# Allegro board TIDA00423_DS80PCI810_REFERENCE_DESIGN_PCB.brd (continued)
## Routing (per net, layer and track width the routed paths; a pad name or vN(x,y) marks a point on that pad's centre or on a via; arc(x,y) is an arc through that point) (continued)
N144795421: length 28.1
  BOTTOM w0.203: C155.2 116.9,46.44 116.9,48.04 118.07,49.21 127.42,49.21 128.56,50.35 128.56,53.83 126.53,55.86 124.14,55.86 122.9,57.11 122.9,60 J2.A76
N144795720: length 39.6
  TOP w0.203: J2.B51 97.37,59.97 97.37,55.89 99.87,53.39 103.7,53.39 104.66,52.42 104.66,48.52 102.78,46.64 102.78,36.2 106.31,32.67 108.76,32.67 109.44,32 109.44,31.19 C112.1
N144796260: length 39.9
  TOP w0.203: C105.1 70.78,31.19 70.78,32.95 73.56,35.73 77.89,35.73 78.65,36.49 78.65,44.9 77.27,46.28 77.27,51.81 79.79,54.33 82.2,54.33 83.95,56.08 83.95,59.95 J2.B37
N144796741: length 28.3
  BOTTOM w0.203: J2.A69 115.37,59.96 115.37,54.74 115.96,54.14 122.27,54.14 123.09,53.32 123.09,51.94 122.24,51.09 115.6,51.09 114.73,50.22 114.73,46.44 C152.2
N144796981: length 28.2
  BOTTOM w0.203: C136.2 69.91,46.45 69.91,49.95 71.5,51.54 83.34,51.54 84.8,53 84.8,55.26 82.38,57.68 82.38,59.98 J2.A36
N144870501: length 4.1
  TOP w0.292: SW2.3 v1(20.38,53.36)
  BOTTOM w0.292: R19.2 20.26,53.24 v1(20.38,53.36)
N144870781: length 3.9
  TOP w0.292: SW2.1 v1(25.46,53.26)
  BOTTOM w0.292: R17.2 v1(25.46,53.26)
N144871281: length 4.1
  TOP w0.292: SW2.2 v1(22.92,53.36)
  BOTTOM w0.292: R18.2 v1(22.92,53.36)
N144872111: length 2.8
  TOP w0.292: SW3.6 v1(30.29,32.43)
  BOTTOM w0.292: R25.2 v1(30.29,32.43)
N144872810: length 2.8
  TOP w0.292: SW3.1 v1(17.59,32.43)
  BOTTOM w0.292: R20.2 v1(17.59,32.43)
N144872811: length 2.8
  TOP w0.292: 20.13,30.77 v1(20.13,32.43)
  BOTTOM w0.292: R21.2 v1(20.13,32.43)
N144872812: length 2.8
  TOP w0.292: SW3.3 v1(22.67,32.43)
  BOTTOM w0.292: R22.2 v1(22.67,32.43)
N144872813: length 2.8
  TOP w0.292: 25.21,30.77 v1(25.21,32.43)
  BOTTOM w0.292: v1(25.21,32.43) 25.08,32.56 R23.2
N144872814: length 2.8
  TOP w0.292: SW3.5 v1(27.75,32.43)
  BOTTOM w0.292: R24.2 v1(27.75,32.43)
N144873671: length 3.1
  TOP w0.292: SW5.4 v1(25.46,19.86)
  BOTTOM w0.292: R29.2 v1(25.46,19.86)
N144874091: length 3.1
  TOP w0.292: SW5.6 v1(30.54,19.86)
  BOTTOM w0.292: R31.2 v1(30.54,19.86)
N144874331: length 3.1
  TOP w0.292: 28,17.95 v1(28,19.86)
  BOTTOM w0.292: R30.2 v1(28,19.86)
N144874811: length 3.1
  TOP w0.292: 22.92,17.95 v1(22.92,19.86)
  BOTTOM w0.292: R28.2 v1(22.92,19.86)
N144875811: length 3.1
  TOP w0.292: 17.84,17.95 v1(17.84,19.86)
  BOTTOM w0.292: R26.2 v1(17.84,19.86)
N144876491: length 3.1
  TOP w0.292: SW5.2 v1(20.38,19.86)
  BOTTOM w0.292: R27.2 v1(20.38,19.86)
N144883340: length 3
  TOP w0.292: SW10.1 v1(159.65,37.06)
  BOTTOM w0.292: R38.2 159.4,36.8 v1(159.65,37.06)
N144883341: length 3.1
  TOP w0.292: SW10.2 v1(159.65,39.6)
  BOTTOM w0.292: R39.2 159.53,39.47 v1(159.65,39.6)
N144883342: length 3.2
  TOP w0.292: SW10.3 v1(159.65,42.14)
  BOTTOM w0.292: v1(159.65,42.14) 159.53,42.01 R40.2
N144883343: length 3.2
  TOP w0.292: SW10.4 v1(159.65,44.68)
  BOTTOM w0.292: R41.2 159.53,44.55 v1(159.65,44.68)
N144883344: length 3.2
  TOP w0.292: SW10.5 v1(159.65,47.22)
  BOTTOM w0.292: R42.2 159.53,47.09 v1(159.65,47.22)
N144883345: length 3.2
  TOP w0.292: SW10.6 v1(159.65,49.76)
  BOTTOM w0.292: v1(159.65,49.76) 159.53,49.63 R43.2
N144883781: length 2.8
  TOP w0.292: SW11.1 v1(159.75,18.77)
  BOTTOM w0.292: R44.2 v1(159.75,18.77)
N144885701: length 2.9
  TOP w0.292: SW6.4 v1(147.31,56.99)
  BOTTOM w0.292: R35.2 147.05,56.74 v1(147.31,56.99)
N144886021: length 2.8
  TOP w0.292: SW11.2 v1(159.75,21.31)
  BOTTOM w0.292: R45.2 v1(159.75,21.31)
N144886681: length 2.9
  TOP w0.292: SW6.6 v1(147.18,62.07)
  BOTTOM w0.292: R37.2 147.05,61.95 v1(147.18,62.07)
N144886921: length 2.8
  TOP w0.292: SW6.5 v1(147.31,59.53)
  BOTTOM w0.292: v1(147.31,59.53) 147.18,59.41 R36.2
N144888121: length 2.8
  TOP w0.292: SW6.3 v1(147.31,54.45)
  BOTTOM w0.292: v1(147.31,54.45) 147.18,54.33 R34.2
N144888661: length 3
  TOP w0.292: SW11.6 v1(159.75,31.47)
  BOTTOM w0.292: R49.2 v1(159.75,31.47)
N144889101: length 2.9
  TOP w0.292: SW11.3 v1(159.75,23.85)
  BOTTOM w0.292: R46.2 v1(159.75,23.85)
N144890181: length 2.9
  TOP w0.292: SW11.4 v1(159.75,26.39)
  BOTTOM w0.292: R47.2 v1(159.75,26.39)
N144890984: length 2.9
  TOP w0.292: SW11.5 v1(159.78,28.93)
  BOTTOM w0.292: R48.2 v1(159.78,28.93)
N144891221: length 2.9
  TOP w0.292: SW6.1 v1(147.31,49.37)
  BOTTOM w0.292: v1(147.31,49.37) 147.05,49.12 R32.2
N144891941: length 2.8
  TOP w0.292: SW6.2 v1(147.31,51.91)
  BOTTOM w0.292: v1(147.31,51.91) 147.18,51.79 R33.2
N144905650: length 1.9
  TOP w0.292: D1.2 R7.1
N144909880: length 1.9
  TOP w0.292: D3.2 R9.1
N144912360: length 1.9
  TOP w0.292: D2.2 R8.1
N144914850: length 1.9
  TOP w0.292: D4.2 R10.1
N708449615: length 39.6
  BOTTOM w0.203: J1.A16 62.92,3.8 62.92,12.35 54.67,20.61 54.67,27.09 59.52,31.94 63.6,31.94 64.17,32.52 64.17,33.06 64.07,33.16 C63.2
N708449616: length 39.6
  BOTTOM w0.203: J1.A17 63.38,3.81 63.38,12.54 55.12,20.8 55.12,26.9 59.7,31.48 63.79,31.48 64.63,32.33 64.63,33.12 C64.2
N708449620: length 39.9
  BOTTOM w0.203: C65.2 65.5,33.12 65.5,32.34 63.88,30.73 60.55,30.73 56.88,27.06 56.88,20.77 67.92,9.73 67.92,3.81 J1.A21
N708449621: length 39.9
  BOTTOM w0.203: J1.A22 68.38,3.81 68.38,9.92 57.34,20.96 57.34,26.87 60.74,30.27 64.07,30.27 65.95,32.15 65.95,33.12 C66.2
N708449624: length 39.8
  BOTTOM w0.203: J1.A25 71.92,3.81 71.92,8.04 59.34,20.62 59.34,27.33 61.63,29.62 64.43,29.62 66.82,32.01 66.82,33.12 C67.2
N708449625: length 39.8
  BOTTOM w0.203: C68.2 67.28,33.12 67.28,31.82 64.62,29.16 61.82,29.16 59.8,27.14 59.8,20.81 72.38,8.23 72.38,3.81 J1.A26
N708449628: length 39.9
  BOTTOM w0.203: J1.A29 75.92,3.81 75.92,6.85 61.25,21.52 61.25,26.79 62.87,28.41 64.83,28.41 68.14,31.73 68.14,33.11 C69.2
N708449629: length 39.9
  BOTTOM w0.203: C70.2 68.6,33.13 68.6,31.54 65.02,27.96 63.06,27.96 61.71,26.61 61.71,21.71 76.38,7.04 76.38,3.81 J1.A30
N708449634: length 39.9
  BOTTOM w0.203: C71.2 69.46,33.11 69.46,30.2 71.62,28.04 75.25,28.04 77.46,25.83 77.46,21.54 75.29,19.38 75.29,13.01 78.55,9.76 80.27,9.76 81.92,8.12 81.92,3.81 J1.A35
N708449635: length 39.9
  BOTTOM w0.203: J1.A36 82.38,3.81 82.38,8.31 80.46,10.22 78.73,10.22 75.75,13.2 75.75,19.19 77.91,21.35 77.91,26.02 75.44,28.5 71.81,28.5 69.92,30.39 69.92,33.12 C72.2
N708449638: length 39.9
  BOTTOM w0.203: J1.A39 85.92,3.81 85.92,9.43 83.6,11.75 80.55,11.75 79.23,13.07 79.23,14.97 79.23,25.52 75.58,29.17 72.09,29.17 70.81,30.45 70.81,33.09 C73.2
N708449639: length 39.9
  BOTTOM w0.203: C74.2 71.27,33.15 71.27,30.64 72.28,29.63 75.77,29.63 79.69,25.71 79.69,15.16 79.69,13.26 80.74,12.21 83.79,12.21 86.38,9.62 86.38,3.81 J1.A40
N708449642: length 40.1
  BOTTOM w0.203: J1.A43 89.92,3.81 89.92,9.95 85.85,14.03 83.71,14.03 80.6,17.13 80.6,25.72 76.05,30.28 73.25,30.28 72.1,31.43 72.1,33.11 C75.2
N708449643: length 40.1
  BOTTOM w0.203: C76.2 72.56,33.13 72.56,31.62 73.44,30.74 76.23,30.74 81.06,25.91 81.06,17.32 83.9,14.48 86.04,14.48 90.38,10.14 90.38,3.81 J1.A44
N708449646: length 39.9
  BOTTOM w0.203: J1.A47 93.92,3.81 93.92,8 81.83,20.1 81.83,26.53 76.96,31.4 74.22,31.4 73.39,32.24 73.39,33.15 C77.2
N708449647: length 40
  BOTTOM w0.203: C78.2 73.84,33.09 73.84,32.42 74.41,31.85 77.15,31.85 82.28,26.72 82.28,20.29 94.38,8.19 94.38,3.81 J1.A48
N708449651: length 39.5
  BOTTOM w0.203: C79.2 108.99,33.11 108.99,32.19 108.1,31.3 105.58,31.3 102.19,27.91 102.19,16.4 100.79,15 98.5,15 96.24,12.74 96.24,8.81 96.92,8.13 97.77,8.13 98.92,6.98 98.92,3.81 J1.A52
N708449652: length 39.5
  BOTTOM w0.203: C80.2 109.44,33.13 109.44,32 108.29,30.84 105.77,30.84 102.65,27.72 102.65,16.21 100.98,14.54 98.69,14.54 96.7,12.55 96.7,9 97.11,8.59 97.96,8.59 99.38,7.17 99.38,3.81 J1.A53
N708449655: length 39.7
  BOTTOM w0.203: J1.A56 102.92,3.81 102.92,7.41 102.06,8.28 100.15,8.28 99.2,9.23 99.2,12.15 100.25,13.2 102.76,13.2 103.46,13.89 103.46,26.52 107.12,30.18 109.03,30.18 110.31,31.46 110.31,33.11 C81.2
N708449656: length 39.7
  BOTTOM w0.203: C82.2 110.77,33.13 110.77,31.27 109.22,29.72 107.31,29.72 103.92,26.33 103.92,13.71 102.95,12.74 100.44,12.74 99.66,11.96 99.66,9.42 100.34,8.73 102.25,8.73 103.38,7.6 103.38,3.81 J1.A57
N708449659: length 40.1
  BOTTOM w0.203: C83.2 111.59,33.15 111.59,30.7 109.95,29.06 107.79,29.06 104.73,26 104.73,16.73 107.85,13.62 107.85,12.82 107.2,12.17 104.91,12.17 104.12,11.38 104.12,9.94 104.95,9.11 106.31,9.11 106.92,8.5 106.92,3.81 J1.A60
N708449660: length 40.1
  BOTTOM w0.203: C84.2 112.05,33.09 112.05,30.51 110.14,28.6 107.98,28.6 105.19,25.81 105.19,16.92 108.31,13.81 108.31,12.63 107.39,11.71 105.1,11.71 104.57,11.19 104.57,10.13 105.14,9.57 106.49,9.57 107.38,8.68 107.38,3.81 J1.A61
N708449663: length 40.2
  BOTTOM w0.203: C85.2 112.97,33.09 112.97,30.86 116.41,27.42 120.18,27.42 121.77,25.83 121.77,20.19 110.92,9.34 110.92,3.81 J1.A64
N708449664: length 40.2
  BOTTOM w0.203: J1.A65 111.38,3.81 111.38,9.15 122.23,20 122.23,26.02 120.37,27.88 116.6,27.88 113.43,31.05 113.43,33.15 C86.2
N708449667: length 40.1
  BOTTOM w0.203: J1.A68 114.89,3.78 114.89,7.02 113.94,7.97 113.94,10.28 122.97,19.31 122.97,26.92 121.49,28.4 117.2,28.4 114.27,31.33 114.27,33.12 C87.2
N708449668: length 40.1
  BOTTOM w0.203: J1.A69 115.35,3.84 115.35,7.21 114.4,8.16 114.4,10.09 123.43,19.12 123.43,27.11 121.68,28.85 117.39,28.85 114.72,31.52 114.72,33.12 C88.2
N708449671: length 39.9
  BOTTOM w0.203: C89.2 115.58,33.12 115.58,31.63 117.79,29.43 122.2,29.43 124.21,27.42 124.21,18.59 116.89,11.27 116.89,9.47 118.92,7.45 118.92,3.81 J1.A72
N708449672: length 39.9
  BOTTOM w0.203: J1.A73 119.38,3.81 119.38,7.64 117.35,9.66 117.35,11.08 124.67,18.4 124.67,27.61 122.39,29.88 117.97,29.88 116.04,31.82 116.04,33.12 C90.2
N708449675: length 39.8
  BOTTOM w0.203: C91.2 116.91,33.11 116.91,32.07 118.51,30.46 123.41,30.46 125.38,28.49 125.38,18.04 119.87,12.53 119.87,10.52 122.92,7.47 122.92,3.81 J1.A76
N708449676: length 39.8
  BOTTOM w0.203: C92.2 117.37,33.13 117.37,32.26 118.7,30.92 123.6,30.92 125.84,28.68 125.84,17.85 120.33,12.34 120.33,10.71 123.38,7.66 123.38,3.81 J1.A77
N708449679: length 39.7
  BOTTOM w0.203: J1.A80 126.92,3.81 126.92,7.62 123.06,11.48 123.06,13.6 126.68,17.22 126.68,29.27 124.42,31.53 118.92,31.53 118.25,32.21 118.25,33.1 C93.2
N708449680: length 39.6
  BOTTOM w0.203: C94.2 118.7,33.14 118.7,32.39 119.11,31.99 124.61,31.99 127.13,29.46 127.13,17.03 123.52,13.41 123.52,11.67 127.38,7.81 127.38,3.81 J1.A81
N708449695: length 28.1
  TOP w0.203: C31.1 64.19,17.86 64.19,16.87 63.81,16.49 55.72,16.49 54.85,15.62 54.85,11.42 55.74,10.53 59.7,10.53 60.92,9.3 60.92,3.81 J1.B14
N708449696: length 28
  TOP w0.203: J1.B15 61.38,3.81 61.38,9.49 59.89,10.98 55.93,10.98 55.3,11.61 55.3,15.43 55.91,16.03 64,16.03 64.65,16.68 64.65,17.9 C32.1
N7084496100: length 28.2
  TOP w0.203: J1.B19 65.92,3.81 65.92,7.68 61.58,12.02 57.59,12.02 56.88,12.73 56.88,14.26 57.48,14.86 64.28,14.86 65.48,16.06 65.48,17.89 C33.1
N7084496101: length 28.2
  TOP w0.203: J1.B20 66.38,3.81 66.38,7.87 61.77,12.48 57.78,12.48 57.34,12.92 57.34,14.07 57.67,14.4 64.47,14.4 65.94,15.87 65.94,17.87 C34.1
N7084496104: length 28.2
  TOP w0.203: C35.1 66.77,17.92 66.77,13.79 66.36,13.37 65,13.37 64.47,12.85 64.47,10.76 64.94,10.29 73.39,10.29 73.72,9.96 73.72,9.51 73.49,9.27 70.86,9.27 69.92,8.34 69.92,3.81 J1.B23
N7084496105: length 28.3
  TOP w0.203: J1.B24 70.38,3.81 70.38,8.15 71.05,8.81 73.68,8.81 74.18,9.32 74.18,10.15 73.58,10.75 65.13,10.75 64.93,10.95 64.93,12.66 65.19,12.92 66.55,12.92 67.23,13.6 67.23,17.84 C36.1
N7084496108: length 28.4
  TOP w0.203: C37.1 68.03,17.92 68.13,17.83 68.13,12.9 69.52,11.51 78.81,11.51 79.08,11.25 79.08,10.28 78.8,10 75.84,10 73.92,8.08 73.92,3.81 73.65,3.54 J1.B27
N7084496109: length 28.4
  TOP w0.203: C38.1 68.59,17.87 68.59,13.09 69.71,11.97 79,11.97 79.53,11.44 79.53,10.09 78.99,9.54 76.03,9.54 74.38,7.89 74.38,3.81 J1.B28
N7084496114: length 28.4
  TOP w0.203: J1.B33 79.92,3.81 79.92,8.18 81.14,9.4 82.09,9.4 82.91,10.22 82.91,11.94 82.04,12.81 71.11,12.81 69.48,14.44 69.48,17.86 C39.1
N7084496115: length 28.4
  TOP w0.203: J1.B34 80.38,3.81 80.38,7.99 81.33,8.94 82.28,8.94 83.37,10.03 83.37,12.13 82.23,13.27 71.3,13.27 69.94,14.63 69.94,17.9 C40.1
N7084496118: length 28.3
  TOP w0.203: J1.B37 83.92,3.81 83.92,8.71 84.46,9.25 85.16,9.25 85.8,9.89 85.8,11.08 82.95,13.92 72.2,13.92 70.79,15.34 70.79,17.87 C41.1
N7084496119: length 28.3
  TOP w0.203: C42.1 71.25,17.89 71.25,15.53 72.39,14.38 83.14,14.38 86.25,11.27 86.25,9.7 85.35,8.79 84.65,8.79 84.38,8.52 84.38,3.81 J1.B38
N7084496122: length 28
  TOP w0.203: C43.1 72.09,17.89 72.09,16.49 73.61,14.98 84,14.98 88.88,10.1 88.88,8.41 87.92,7.44 87.92,3.81 J1.B41
N7084496123: length 28
  TOP w0.203: J1.B42 88.38,3.81 88.38,7.25 89.34,8.22 89.34,10.29 84.19,15.44 73.8,15.44 72.55,16.68 72.55,17.87 C44.1
N7084496126: length 28.4
  TOP w0.203: J1.B45 91.92,3.81 91.92,8.87 84.41,16.38 73.97,16.38 73.41,16.94 73.41,17.89 C45.1
N7084496127: length 28.4
  TOP w0.203: C46.1 73.86,17.87 73.86,17.13 74.16,16.84 84.6,16.84 92.38,9.06 92.38,3.81 J1.B46
N7084496131: length 28.1
  TOP w0.203: J1.B50 96.92,3.81 96.92,7.29 95.92,8.28 94.81,8.28 94.18,8.91 94.18,12.14 95.38,13.34 99.87,13.34 103.63,17.1 108.66,17.1 109.03,17.47 109.03,17.73 108.93,17.83 C47.1
N7084496132: length 28.1
  TOP w0.203: J1.B51 97.38,3.81 97.38,7.47 96.11,8.74 95,8.74 94.64,9.1 94.64,11.96 95.57,12.88 100.06,12.88 103.82,16.64 108.85,16.64 109.49,17.28 109.49,17.88 C48.1
N7084496135: length 28.3
  TOP w0.203: C49.1 110.36,17.87 110.36,16.78 109.57,15.99 104.07,15.99 100.25,12.17 97.44,12.17 96.87,11.6 96.87,9.77 97.39,9.26 100.12,9.26 100.92,8.45 100.92,3.81 J1.B54
N7084496136: length 28.3
  TOP w0.203: J1.B55 101.38,3.81 101.38,8.64 100.3,9.71 97.58,9.71 97.33,9.96 97.33,11.41 97.63,11.71 100.44,11.71 104.26,15.53 109.76,15.53 110.82,16.59 110.82,17.89 C50.1
N7084496139: length 28.3
  TOP w0.203: J1.B58 104.92,3.81 104.92,7.37 105.75,8.2 106.66,8.2 107.11,8.65 107.11,9.19 106.75,9.55 102.64,9.55 101.74,10.44 101.74,11.67 102.66,12.59 103.69,12.59 104.17,13.07 104.17,14.04 104.94,14.81 110.01,14.81 111.63,16.43 111.63,17.92 C51.1
N7084496140: length 28.4
  TOP w0.203: J1.B59 105.38,3.81 105.38,7.18 105.94,7.74 106.85,7.74 107.57,8.46 107.57,9.38 106.94,10.01 102.83,10.01 102.2,10.63 102.2,11.48 102.85,12.13 103.88,12.13 104.62,12.88 104.62,13.85 105.13,14.36 110.2,14.36 112.09,16.24 112.09,17.84 C52.1
N7084496143: length 28.1
  TOP w0.203: C53.1 112.99,17.88 112.99,15.89 110.68,13.58 105.91,13.58 105.17,12.84 105.17,11.45 105.97,10.65 111.12,10.65 111.43,10.34 111.43,9.63 111.09,9.29 109.74,9.29 108.92,8.47 108.92,3.81 J1.B62
N7084496144: length 28.1
  TOP w0.203: J1.B63 109.38,3.81 109.38,8.28 109.93,8.83 111.28,8.83 111.89,9.44 111.89,10.53 111.31,11.11 106.16,11.11 105.63,11.64 105.63,12.65 106.1,13.12 110.87,13.12 113.45,15.7 113.45,17.88 C54.1
N7084496147: length 28.2
  TOP w0.203: C55.1 114.35,17.85 114.35,13.78 113.99,13.42 112.57,13.42 111.98,12.83 111.98,11.63 112.49,11.12 118.54,11.12 119.01,10.65 119.01,9.47 118.55,9.01 113.74,9.01 112.9,8.17 112.9,3.79 J1.B66
N7084496148: length 28.2
  TOP w0.203: C56.1 114.8,17.91 114.8,13.59 114.18,12.96 112.76,12.96 112.44,12.64 112.44,11.82 112.68,11.58 118.73,11.58 119.46,10.84 119.46,9.28 118.74,8.55 113.93,8.55 113.36,7.98 113.36,3.83 J1.B67
N7084496151: length 28.4
  TOP w0.203: J1.B70 116.92,3.81 116.92,6.84 118.03,7.95 119.89,7.95 120.65,8.72 120.65,11.1 121.51,11.96 124.01,11.96 124.5,12.44 124.5,13.05 123.92,13.63 116.38,13.63 115.6,14.41 115.6,17.91 C57.1
N7084496152: length 28.4
  TOP w0.203: C58.1 116.06,17.85 116.06,14.6 116.57,14.08 124.11,14.08 124.95,13.24 124.95,12.25 124.2,11.5 121.7,11.5 121.11,10.91 121.11,8.53 120.08,7.49 118.22,7.49 117.38,6.65 117.38,3.81 J1.B71
N7084496155: length 28.3
  TOP w0.203: J1.B74 120.92,3.81 120.92,7.49 124.34,10.91 126.78,10.91 127.36,11.48 127.36,13.99 126.27,15.07 117.32,15.07 116.95,15.45 116.95,17.88 C59.1
N7084496156: length 28.3
  TOP w0.203: C60.1 117.41,17.88 117.41,15.64 117.51,15.53 126.46,15.53 127.82,14.18 127.82,11.3 126.97,10.45 124.53,10.45 121.38,7.3 121.38,3.81 J1.B75
N7084496159: length 28.2
  TOP w0.203: J1.B78 124.92,3.81 124.92,7.34 128.12,10.53 129.25,10.53 129.92,11.2 129.92,15.52 129.13,16.31 118.86,16.31 118.28,16.88 118.28,17.87 C61.1
N7084496160: length 28.2
  TOP w0.203: C62.1 118.74,17.89 118.74,17.07 119.05,16.76 129.32,16.76 130.38,15.71 130.38,11.01 129.44,10.08 128.31,10.08 125.38,7.15 125.38,3.81 J1.B79

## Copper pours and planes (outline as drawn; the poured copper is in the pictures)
12V on POWER2: 34.35,5.54 34.35,13.79 33.41,13.79 33.41,62.86 42.28,62.86 42.28,58.54 48.76,58.54 48.76,20.97 50.51,19.22 50.51,5.91 46.01,5.91 46.01,10.95 43.16,13.79 40.32,10.95 40.32,5.54
GND on TOP: 64.65,38.67 64.65,40.94 65.54,41.83 71.57,41.83 71.76,41.64 71.76,38.43 71.23,37.9 70,37.9 69.68,37.59 65.74,37.59
GND on TOP: 85.51,42.57 85.51,39.54 87.85,39.54 87.85,42.57
GND on TOP: 86.02,23.67 86.02,20.7 88.38,20.7 88.38,23.67
GND on TOP: 117.61,39.25 115.99,37.62 110.32,37.62 109.48,38.47 109.48,41.15 110.19,41.86 117.04,41.86 117.61,41.3
GND on BOTTOM: 116.63,25.92 116.63,22.74 116.38,22.49 110.33,22.49 109.49,23.34 109.49,25.66 110.55,26.72 115.83,26.72
GND on BOTTOM: 72.84,25.42 72.84,22.98 72.21,22.34 65.56,22.34 64.96,22.95 64.96,25.62 65.93,26.6 71.66,26.6
GND on GND1, GND2: 132.88,3.73 132.82,3.79 132.82,7.62 130.68,9.75 128.55,7.62 128.55,5.91 58.86,5.91 58.86,7.47 57.15,9.18 55.44,7.47 55.44,5.91 45.75,5.91 45.75,10.95 43.16,13.53 40.57,10.95 40.57,5.28 34.1,5.28 34.1,13.53 14.24,13.53 14.24,5.28 0.76,5.28 0.76,67.06 42.28,67.06 42.28,58.54 131.66,58.54 131.66,67.06 166.88,67.06 166.88,13.53 140.79,13.53 139.01,12.8 138.28,11.02 138.28,9.72 139.01,7.94 140.79,7.21 143.99,7.21 143.99,5.59 142.92,3.73
VDD1 on POWER2: 62.3,18.79 58.74,22.35 58.74,32.15 72.98,32.15 74.63,30.5 85.97,30.5 86.5,29.97 86.5,25.94 86.07,25.5 86.07,22.51 82.35,18.79
VDD2 on POWER2: 102.43,18.95 100.34,21.03 100.34,28.22 99.41,29.16 96.05,29.16 93.84,26.95 88.05,26.95 88.05,32.33 88.74,33.02 100.72,33.02 104.02,29.71 117.92,29.71 118.2,29.44 118.2,20.4 116.75,18.95
VDD3 on POWER2: 58.74,32.92 58.74,49.98 88.89,49.98 88.89,43.59 87.56,42.26 74.1,42.26 72.76,40.92 72.76,32.92
VDD4 on POWER2: 108.86,35.81 102.41,42.26 88.64,42.26 89.65,43.27 89.65,49.98 118.43,49.98 118.43,37.52 116.72,35.81
VDD_SEL3_4 on POWER2: 118.4,30.48 104.34,30.48 101.03,33.78 88.43,33.78 87.29,32.64 87.29,31.17 87.19,31.26 74.95,31.26 73.52,32.69 73.52,40.61 74.42,41.5 102.09,41.5 108.54,35.05 117.04,35.05 119.19,37.2 119.19,49.98 128.79,49.98 131.66,47.11 131.66,32.06 128.58,28.98 119.9,28.98
3_3V on POWER1: 81.95,39.39 81.95,43.79 82.77,44.6 98.97,44.6 100.01,43.56 100.01,19.2 98.72,17.9 86.25,17.9 84.77,19.38 84.77,36.57
3_3V on POWER2: 51.27,5.91 51.27,19.53 49.52,21.29 49.52,58.54 57.98,58.54 57.98,22.04 61.98,18.03 82.67,18.03 86.83,22.19 86.83,25.19 87.83,26.18 94.15,26.18 96.36,28.39 99.09,28.39 99.58,27.91 99.58,21.03 99.12,20.57 95.59,20.57 93.13,18.11 93.13,5.91 59.12,5.91 59.12,7.47 57.15,9.43 55.18,7.47 55.18,5.91
VIH on POWER1: 61.36,53.89 61.68,53.57 61.68,45.59 59.55,43.46 59.5,43.46 59.07,43.02 34.07,43.02 29.73,47.37 29.73,52.37 30.16,52.8 31.13,52.8 32.17,51.76 35.22,51.76 37.35,53.89
VIH on POWER2: 133.07,3.98 133.07,7.62 130.68,10.01 128.3,7.62 128.3,5.91 93.89,5.91 93.89,17.8 95.9,19.81 99.43,19.81 99.96,20.34 102.12,18.18 117.06,18.18 118.96,20.08 118.96,27.71 119.47,28.22 128.9,28.22 132.42,31.74 132.42,47.42 129.1,50.75 89.5,50.75 89.43,50.82 89.11,50.82 89.03,50.75 58.74,50.75 58.74,58.54 135.47,58.54 135.47,64.23 162.34,64.23 162.34,15.06 140.93,15.06 138.97,13.1 138.27,12.16 138.02,11.02 138.02,9.72 138.83,7.76 140.79,6.95 143.74,6.95 143.74,5.66 142.77,3.98
VIH on POWER2: 15.08,13.79 15.08,62.81 32.65,62.81 32.65,13.79
VOUT1_2 on TOP: 89.07,20.9 90.92,20.9 91.12,20.7 91.12,19.83 91.45,19.5 93.23,19.5 93.38,19.35 93.92,19.35 94.04,19.48 94.5,19.48 94.81,19.78 99.15,19.78 99.84,20.47 99.84,25.85 98.67,27.02 86.96,27.02 86.41,27.57 86.41,30.92 87.06,31.57 101.16,31.57 103.29,29.44 103.29,19.15 99.1,14.96 89.7,14.96 88.79,15.87 88.79,20.62 ; 2 cut-outs
VOUT3_4 on TOP: 88.56,39.87 90.41,39.87 91.2,39.09 92.47,39.09 92.55,39.01 93.38,39.01 93.84,39.47 93.84,43.25 92.72,44.37 89.09,44.37 88.56,44.9 88.56,48 88.84,48.28 95.49,48.28 97.09,46.68 97.09,38.53 96.46,37.89 94.68,37.89 93.56,36.78 88.79,36.78 88.28,37.28 88.28,39.6

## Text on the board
BOTTOM: BOTTOM
Ref Des/Assembly Bottom: A1 | A82 | BOTTOM ASSEMBLY
Board Geometry/Soldermask Bottom: BOTTOM MASK
Ref Des/Silkscreen Bottom: A | B | MAR 2013 | 305-PD13-0341 | A1 | A82 | BOTTOM SILK
User.Comments: 2713 | 2535 | 2122 | 591 | 2250 | 1955 | 459 | 144 | 6600 | 2841 | 2949 | 3224 | 354 | 2XR69 | 55 | 500 | 189 | 386
TOP: TOP
Ref Des/Assembly Top: B1 | B82 | TOP ASSEMBLY
Board Geometry/Soldermask Top: TOP MASK
Ref Des/Silkscreen Top: 1-VDD1 | 2-2.5V | 3-2.5V | 4-VDD2 | VODB0/VODB1(US) | J4 | 1-VDD3 | 4-VDD4 | J6 | VODB0_AD1/VODB1_AD0(DS) | VODA0/VODA1(US) | VODA0/VODA1(DS) | 1-3.3V | 2-VIH | J7 | 4-SDA | 1-GND | 2-NC | 3-SCL | J8 | 3.3V | V1N3_4 | A_D1-RD_EN2 to A_D4-PRSNT | READ_EN/RD_EN2 | SD_TH/RES1 | ON | EQA/RES3(US) | OFF | ENSMB | EQB_AD3/AD2 | SMCLK-SCL/SMDAT-SDA | SDA/SCL | VDD_SEL1_2/VDD_SEL3_4 | READ_EN | RXDET/RES2 | 4.99K_GND | 249_VIH | 249_GND | 1 | 3 | 2 | 4 | 6 | 5 | 7 | 9 | 8 | 10 | 12 | 11 | SIG | B1 | V1N1_2 | A | B | B82 | PRSNT | TIDA00423 | TOP SILK
GND1: GND1
POWER1: POWER1
POWER2: POWER2
GND2: GND2
DISPLAY_BOTTOM: 7 MIL | 1.4 MIL | 31.6 MIL | 4 MIL | SILKSCREEN (BOTTOM SIDE) | SOLDERMASK (BOTTOM SIDE) | SOLDERMASK (TOP SIDE) | SILKSCREEN (TOP SIDE) | GND1 | POWER1 | PREPEG | BOTTOM - COPPER + PLATING = 1.4 MIL FINISHED THICKNESS | GND2 | TOP - COPPER + PLATING = 1.4 MIL FINISHED THICKNESS TOP | POWER2 | CORE | C | NOTES: (UNLESS OTHERWISE SPECIFIED) | ~~~~~~~~~~~~~~~~~~~~~~~~~~~~~~~~~~~~~~~~~ | 17. IMPEDANCE DETAILS: | 16. ANY CHANGES MADE TO THE FILM OR GERBERS MUST BE APPROVED BY PACTRON. | 15. BOARD DIMENSION ARE IN INCHES. | 10. NO VENDOR LOGO OR NAME ON THE BOARD | 12. TOOLING HOLE: SHALL BE DRILLED FIRST AND PLUGGED DURING PLATING. | 13. REMOVE NON FUNCTIONAL PADS ON INNER LAYERS. | 11.DRILLING: | 14. CLIP THE SILKSCREEN OVER SOLDERMASK. | 1.BOARD THICKNESS: 62 MILS +2/-0 TOL | 2.MATERIAL:FR4 | 3.ALL COPPER LAYERS SHALL BE 1 OUNCE (1.4 MIL) FINISHED THICKNESS. | 4.FINISH: | 5.SOLDERMASK : LPI GREEN (MAINTAIN THICKNESS 1 MIL ON BOTH SIDES). | 6.SILK SCREENS BOTH SIDES SHALL BE WHITE. | 7.BOARD TWIST AND WARP SHALL NOT EXCEED 4MILS/LINEAR INCH | 8.EACH ASSEMBLED BOARD MUST BE PACKAGED IN A ESD BAG AND SEALED WITH AN ESD LABEL | 9.FINISHED BOARD IS ROHS COMPLIANT AND LEAD FREE. | 11.5 MIL TRACES IN ALL LAYERS REQUIRE 50 OHM IMPEDANCE +/-5 %TOL | 8 MIL TRACE WIDTH WITH 10 MIL AIRGAP IN TOP AND BOTTOM REQUIRES 100 OHM DIFFERENTIAL CONTROLLED IMPEDANCE  +/-5 % TOL | 11.1 ALL HOLE DIAMETERS ARE FINISHED SIZES. | 11.2 ALL HOLES TO BE +/- .003 FROM TRUE POSITION UNLESS OTHERWISE SPECIFIED. | 4A .HARD GOLD (25-40 MICRONS) OVER HARD NICKEL PLATING BOTH SIDES. | 4B .REST OF THE CIRCUITRY WILL BE SOFT IMMERSION GOLD | 4C .HARD GOLD (10-15 MICRONS) OVER HARD NICKEL PLATING BOTH SIDES. | LAYER STACKUP-6 LAYERS | FILM LAYERS ARE SHOWN AS | VIEWED FROM THE TOP SIDE | OF THE BOARD. | REVISIONS | DATE | TITLE: | DRAWN | QC | TIDA00423 DS80PCI810 PCIe Gen 3 Riser Card | JAN 2015 | DATED | UNITS: | 305-PD-13-0341 | REV | SIZE | 1
DISPLAY_TOP: DATE: JAN 2015 | TIDA00423_DS80PCI810_REFERENCE_DESIGN | LAYER | LAYER: | JOB:305-PD-13-0341 | REV:1 | TEXAS INSTRUMENTS
User.5: NOT TO SCALE | 2 X 0.02X45deg | 0.531 | 0.039 TYP. | 3.4250 | DETAIL-A | 0.039 | 0.200 | 0.276 MAX | 30deg | 0.020 | 0.062 | -0.000 | +0.002 | FAB | CHAMBER EDGES MUST BE FREE OF CUTTING BURRS | DETAIL-A & 4C | EDGE CONNECTOR | TYP0.062 | PROFILE | TYP 20 deg | FINGER DETAIL | TYP 0.051 | DETAIL-B & 4A | DETAIL-B | .5mm X 45 DEGREES | COMPANY: TEXAS INSTRUMENTS
User.9: GND1#2
User.11: PWR#4
User.12: GND2#5
User.24: FIGURE | SIZE | 10.0 | 39.37 | 40.0 | 125.0 | DRILL CHART: TOP to BOTTOM | ALL UNITS ARE IN MILS | TOLERANCE | +3.0/-3.0 | PLATED | QTY | 389 | 20 | 8 | 2 | 19
User.31: BOTTOM PASTE
User.32: TOP PASTE
